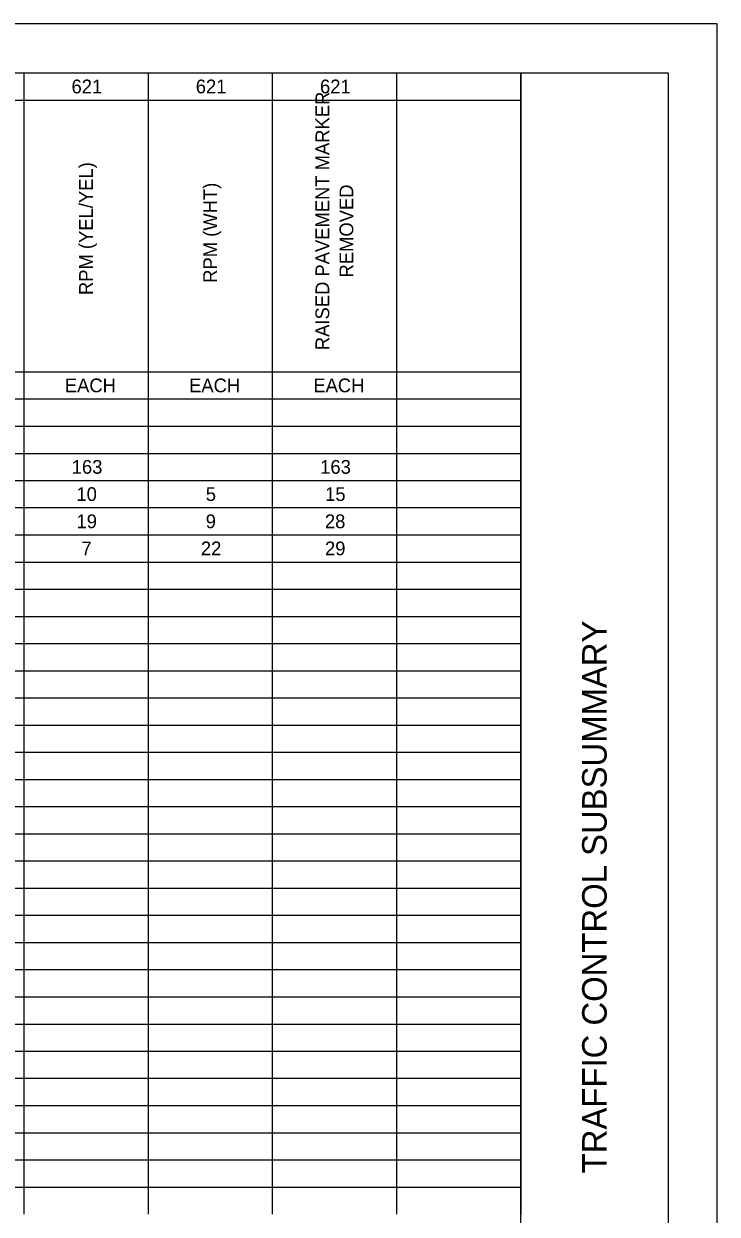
# Model space of a CAD drawing. Extents: x 0 to 34, y 0 to 22.
# Drawn here: x 26.94 to 34, y 9.88 to 22 of the extents above; entities that cross this region are included whole.
import ezdxf

# ---------------------------------------------------------------- set-up
doc = ezdxf.new("R2010")
doc.units = 0
for name, color, linetype in [('SH_Border', 7, 'Continuous'), ('SH_Cut_Line', 7, 'Continuous'), ('SH_Data', 7, 'Continuous'), ('SH_Text', 7, 'Continuous')]:
    doc.layers.add(name, color=color, linetype=linetype)

msp = doc.modelspace()

# ---------------------------------------------------------------- linework, layer by layer
at = {"layer": 'SH_Border'}
msp.add_line((32, 0.5), (32, 21.5), dxfattribs=at)
msp.add_lwpolyline([(1.5, 21.5), (33.5, 21.5), (33.5, 0.5), (1.5, 0.5)], close=True, dxfattribs=at)
at = {"layer": 'SH_Cut_Line'}
msp.add_lwpolyline([(0, 0), (34, 0), (34, 22), (0, 22)], close=True, dxfattribs=at)
at = {"layer": 'SH_Text'}
for p, q in [((25.675, 21.5), (26.94, 21.5)), ((26.94, 21.5), (28.205, 21.5)), ((26.94, 21.5), (26.94, 21.223)), ((28.205, 21.5), (29.47, 21.5)), ((28.205, 21.5), (28.205, 21.223)), ((29.47, 21.5), (30.735, 21.5)), ((29.47, 21.5), (29.47, 21.223)), ((30.735, 21.5), (32, 21.5)), ((30.735, 21.5), (30.735, 21.223)), ((32, 21.5), (32, 21.223)), ((25.675, 21.223), (26.94, 21.223)), ((26.94, 21.223), (28.205, 21.223)), ((26.94, 21.223), (26.94, 20.947)), ((28.205, 21.223), (29.47, 21.223)), ((28.205, 21.223), (28.205, 20.947)), ((29.47, 21.223), (30.735, 21.223)), ((29.47, 21.223), (29.47, 20.947)), ((30.735, 21.223), (32, 21.223)), ((30.735, 21.223), (30.735, 20.947)), ((32, 21.223), (32, 20.947)), ((26.94, 20.947), (26.94, 20.67)), ((28.205, 20.947), (28.205, 20.67)), ((29.47, 20.947), (29.47, 20.67)), ((30.735, 20.947), (30.735, 20.67)), ((32, 20.947), (32, 20.67)), ((26.94, 20.67), (26.94, 20.393)), ((28.205, 20.67), (28.205, 20.393)), ((29.47, 20.67), (29.47, 20.393)), ((30.735, 20.67), (30.735, 20.393)), ((32, 20.67), (32, 20.393)), ((26.94, 20.393), (26.94, 20.116)), ((28.205, 20.393), (28.205, 20.116)), ((29.47, 20.393), (29.47, 20.116)), ((30.735, 20.393), (30.735, 20.116)), ((32, 20.393), (32, 20.116)), ((26.94, 20.116), (26.94, 19.84)), ((28.205, 20.116), (28.205, 19.84)), ((29.47, 20.116), (29.47, 19.84)), ((30.735, 20.116), (30.735, 19.84)), ((32, 20.116), (32, 19.84)), ((26.94, 19.84), (26.94, 19.563)), ((28.205, 19.84), (28.205, 19.563)), ((29.47, 19.84), (29.47, 19.563)), ((30.735, 19.84), (30.735, 19.563)), ((32, 19.84), (32, 19.563)), ((26.94, 19.563), (26.94, 19.01)), ((28.205, 19.563), (28.205, 19.01)), ((29.47, 19.563), (29.47, 19.01)), ((30.735, 19.563), (30.735, 19.01)), ((32, 19.563), (32, 19.01)), ((26.94, 19.01), (26.94, 18.18)), ((28.205, 19.01), (28.205, 18.18)), ((29.47, 19.01), (29.47, 18.18)), ((30.735, 19.01), (30.735, 18.18)), ((32, 19.01), (32, 18.18)), ((25.675, 18.456), (26.94, 18.456)), ((26.94, 18.456), (28.205, 18.456)), ((28.205, 18.456), (29.47, 18.456)), ((29.47, 18.456), (30.735, 18.456)), ((30.735, 18.456), (32, 18.456)), ((25.675, 18.18), (26.94, 18.18)), ((26.94, 18.18), (28.205, 18.18)), ((26.94, 18.18), (26.94, 17.349)), ((28.205, 18.18), (29.47, 18.18)), ((28.205, 18.18), (28.205, 17.349)), ((29.47, 18.18), (30.735, 18.18)), ((29.47, 18.18), (29.47, 17.349)), ((30.735, 18.18), (32, 18.18)), ((30.735, 18.18), (30.735, 17.349)), ((32, 18.18), (32, 17.349)), ((25.675, 17.903), (26.94, 17.903)), ((26.94, 17.903), (28.205, 17.903)), ((28.205, 17.903), (29.47, 17.903)), ((29.47, 17.903), (30.735, 17.903)), ((30.735, 17.903), (32, 17.903)), ((25.675, 17.626), (26.94, 17.626)), ((26.94, 17.626), (28.205, 17.626)), ((28.205, 17.626), (29.47, 17.626)), ((29.47, 17.626), (30.735, 17.626)), ((30.735, 17.626), (32, 17.626)), ((25.675, 17.349), (26.94, 17.349)), ((26.94, 17.349), (28.205, 17.349)), ((26.94, 17.349), (26.94, 17.073)), ((28.205, 17.349), (29.47, 17.349)), ((28.205, 17.349), (28.205, 17.073)), ((29.47, 17.349), (30.735, 17.349)), ((29.47, 17.349), (29.47, 17.073)), ((30.735, 17.349), (32, 17.349)), ((30.735, 17.349), (30.735, 17.073)), ((32, 17.349), (32, 17.073)), ((25.675, 17.073), (26.94, 17.073)), ((26.94, 17.073), (28.205, 17.073)), ((26.94, 17.073), (26.94, 15.966)), ((28.205, 17.073), (29.47, 17.073)), ((28.205, 17.073), (28.205, 15.966)), ((29.47, 17.073), (30.735, 17.073)), ((29.47, 17.073), (29.47, 15.966)), ((30.735, 17.073), (32, 17.073)), ((30.735, 17.073), (30.735, 15.966)), ((32, 17.073), (32, 15.966)), ((25.675, 16.796), (26.94, 16.796)), ((26.94, 16.796), (28.205, 16.796)), ((28.205, 16.796), (29.47, 16.796)), ((29.47, 16.796), (30.735, 16.796)), ((30.735, 16.796), (32, 16.796)), ((25.675, 16.519), (26.94, 16.519)), ((26.94, 16.519), (28.205, 16.519)), ((28.205, 16.519), (29.47, 16.519)), ((29.47, 16.519), (30.735, 16.519)), ((30.735, 16.519), (32, 16.519)), ((25.675, 16.243), (26.94, 16.243)), ((26.94, 16.243), (28.205, 16.243)), ((28.205, 16.243), (29.47, 16.243)), ((29.47, 16.243), (30.735, 16.243)), ((30.735, 16.243), (32, 16.243)), ((25.675, 15.966), (26.94, 15.966)), ((26.94, 15.966), (28.205, 15.966)), ((26.94, 15.966), (26.94, 15.689)), ((28.205, 15.966), (29.47, 15.966)), ((28.205, 15.966), (28.205, 15.689)), ((29.47, 15.966), (30.735, 15.966)), ((29.47, 15.966), (29.47, 15.689)), ((30.735, 15.966), (32, 15.966)), ((30.735, 15.966), (30.735, 15.689)), ((32, 15.966), (32, 15.689)), ((25.675, 15.689), (26.94, 15.689)), ((26.94, 15.689), (28.205, 15.689)), ((26.94, 15.689), (26.94, 15.136)), ((28.205, 15.689), (29.47, 15.689)), ((28.205, 15.689), (28.205, 15.136)), ((29.47, 15.689), (30.735, 15.689)), ((29.47, 15.689), (29.47, 15.136)), ((30.735, 15.689), (32, 15.689)), ((30.735, 15.689), (30.735, 15.136)), ((32, 15.689), (32, 15.136)), ((25.675, 15.412), (26.94, 15.412)), ((26.94, 15.412), (28.205, 15.412)), ((28.205, 15.412), (29.47, 15.412)), ((29.47, 15.412), (30.735, 15.412)), ((30.735, 15.412), (32, 15.412)), ((25.675, 15.136), (26.94, 15.136)), ((26.94, 15.136), (28.205, 15.136)), ((26.94, 15.136), (26.94, 14.582)), ((28.205, 15.136), (29.47, 15.136)), ((28.205, 15.136), (28.205, 14.582)), ((29.47, 15.136), (30.735, 15.136)), ((29.47, 15.136), (29.47, 14.582)), ((30.735, 15.136), (32, 15.136)), ((30.735, 15.136), (30.735, 14.582)), ((32, 15.136), (32, 14.582)), ((25.675, 14.859), (26.94, 14.859)), ((26.94, 14.859), (28.205, 14.859)), ((28.205, 14.859), (29.47, 14.859)), ((29.47, 14.859), (30.735, 14.859)), ((30.735, 14.859), (32, 14.859)), ((25.675, 14.582), (26.94, 14.582)), ((26.94, 14.582), (28.205, 14.582)), ((26.94, 14.582), (26.94, 14.306)), ((28.205, 14.582), (29.47, 14.582)), ((28.205, 14.582), (28.205, 14.306)), ((29.47, 14.582), (30.735, 14.582)), ((29.47, 14.582), (29.47, 14.306)), ((30.735, 14.582), (32, 14.582)), ((30.735, 14.582), (30.735, 14.306)), ((32, 14.582), (32, 14.306)), ((25.675, 14.306), (26.94, 14.306)), ((26.94, 14.306), (28.205, 14.306)), ((26.94, 14.306), (26.94, 13.752)), ((28.205, 14.306), (29.47, 14.306)), ((28.205, 14.306), (28.205, 13.752)), ((29.47, 14.306), (30.735, 14.306)), ((29.47, 14.306), (29.47, 13.752)), ((30.735, 14.306), (32, 14.306)), ((30.735, 14.306), (30.735, 13.752)), ((32, 14.306), (32, 13.752)), ((25.675, 14.029), (26.94, 14.029)), ((26.94, 14.029), (28.205, 14.029)), ((28.205, 14.029), (29.47, 14.029)), ((29.47, 14.029), (30.735, 14.029)), ((30.735, 14.029), (32, 14.029)), ((25.675, 13.752), (26.94, 13.752)), ((26.94, 13.752), (28.205, 13.752)), ((26.94, 13.752), (26.94, 13.476)), ((28.205, 13.752), (29.47, 13.752)), ((28.205, 13.752), (28.205, 13.476)), ((29.47, 13.752), (30.735, 13.752)), ((29.47, 13.752), (29.47, 13.476)), ((30.735, 13.752), (32, 13.752)), ((30.735, 13.752), (30.735, 13.476)), ((32, 13.752), (32, 13.476)), ((25.675, 13.476), (26.94, 13.476)), ((26.94, 13.476), (28.205, 13.476)), ((26.94, 13.476), (26.94, 12.645)), ((28.205, 13.476), (29.47, 13.476)), ((28.205, 13.476), (28.205, 12.645)), ((29.47, 13.476), (30.735, 13.476)), ((29.47, 13.476), (29.47, 12.645)), ((30.735, 13.476), (32, 13.476)), ((30.735, 13.476), (30.735, 12.645)), ((32, 13.476), (32, 12.645)), ((25.675, 13.199), (26.94, 13.199)), ((26.94, 13.199), (28.205, 13.199)), ((28.205, 13.199), (29.47, 13.199)), ((29.47, 13.199), (30.735, 13.199)), ((30.735, 13.199), (32, 13.199)), ((25.675, 12.922), (26.94, 12.922)), ((26.94, 12.922), (28.205, 12.922)), ((28.205, 12.922), (29.47, 12.922)), ((29.47, 12.922), (30.735, 12.922)), ((30.735, 12.922), (32, 12.922)), ((25.675, 12.645), (26.94, 12.645)), ((26.94, 12.645), (28.205, 12.645)), ((26.94, 12.645), (26.94, 12.369)), ((28.205, 12.645), (29.47, 12.645)), ((28.205, 12.645), (28.205, 12.369)), ((29.47, 12.645), (30.735, 12.645)), ((29.47, 12.645), (29.47, 12.369)), ((30.735, 12.645), (32, 12.645)), ((30.735, 12.645), (30.735, 12.369)), ((32, 12.645), (32, 12.369)), ((25.675, 12.369), (26.94, 12.369)), ((26.94, 12.369), (28.205, 12.369)), ((26.94, 12.369), (26.94, 12.092)), ((28.205, 12.369), (29.47, 12.369)), ((28.205, 12.369), (28.205, 12.092)), ((29.47, 12.369), (30.735, 12.369)), ((29.47, 12.369), (29.47, 12.092)), ((30.735, 12.369), (32, 12.369)), ((30.735, 12.369), (30.735, 12.092)), ((32, 12.369), (32, 12.092)), ((25.675, 12.092), (26.94, 12.092)), ((26.94, 12.092), (28.205, 12.092)), ((26.94, 12.092), (26.94, 11.262)), ((28.205, 12.092), (29.47, 12.092)), ((28.205, 12.092), (28.205, 11.262)), ((29.47, 12.092), (30.735, 12.092)), ((29.47, 12.092), (29.47, 11.262)), ((30.735, 12.092), (32, 12.092)), ((30.735, 12.092), (30.735, 11.262)), ((32, 12.092), (32, 11.262)), ((25.675, 11.815), (26.94, 11.815)), ((26.94, 11.815), (28.205, 11.815)), ((28.205, 11.815), (29.47, 11.815)), ((29.47, 11.815), (30.735, 11.815)), ((30.735, 11.815), (32, 11.815)), ((25.675, 11.539), (26.94, 11.539)), ((26.94, 11.539), (28.205, 11.539)), ((28.205, 11.539), (29.47, 11.539)), ((29.47, 11.539), (30.735, 11.539)), ((30.735, 11.539), (32, 11.539)), ((25.675, 11.262), (26.94, 11.262)), ((26.94, 11.262), (28.205, 11.262)), ((26.94, 11.262), (26.94, 10.708)), ((28.205, 11.262), (29.47, 11.262)), ((28.205, 11.262), (28.205, 10.708)), ((29.47, 11.262), (30.735, 11.262)), ((29.47, 11.262), (29.47, 10.708)), ((30.735, 11.262), (32, 11.262)), ((30.735, 11.262), (30.735, 10.708)), ((32, 11.262), (32, 10.708)), ((25.675, 10.985), (26.94, 10.985)), ((26.94, 10.985), (28.205, 10.985)), ((28.205, 10.985), (29.47, 10.985)), ((29.47, 10.985), (30.735, 10.985)), ((30.735, 10.985), (32, 10.985)), ((25.675, 10.708), (26.94, 10.708)), ((26.94, 10.708), (28.205, 10.708)), ((26.94, 10.708), (26.94, 9.878)), ((28.205, 10.708), (29.47, 10.708)), ((28.205, 10.708), (28.205, 9.878)), ((29.47, 10.708), (30.735, 10.708)), ((29.47, 10.708), (29.47, 9.878)), ((30.735, 10.708), (32, 10.708)), ((30.735, 10.708), (30.735, 9.878)), ((32, 10.708), (32, 9.878)), ((25.675, 10.432), (26.94, 10.432)), ((26.94, 10.432), (28.205, 10.432)), ((28.205, 10.432), (29.47, 10.432)), ((29.47, 10.432), (30.735, 10.432)), ((30.735, 10.432), (32, 10.432)), ((25.675, 10.155), (26.94, 10.155)), ((26.94, 10.155), (28.205, 10.155)), ((28.205, 10.155), (29.47, 10.155)), ((29.47, 10.155), (30.735, 10.155)), ((30.735, 10.155), (32, 10.155))]:
    msp.add_line(p, q, dxfattribs=at)

# ---------------------------------------------------------------- texts
at = {"layer": 'SH_Data'}
msp.add_text('TRAFFIC CONTROL SUBSUMMARY', height=0.25, rotation=90, dxfattribs=at).set_placement((32.875, 10.295))
at = {"layer": 'SH_Text'}
for s, p in [('621', (27.426, 21.292)), ('621', (28.691, 21.292)), ('621', (29.956, 21.292)), ('EACH', (27.358, 18.248)), ('EACH', (28.623, 18.248)), ('EACH', (29.888, 18.248)), ('163', (27.428, 17.418)), ('163', (29.958, 17.418)), ('10', (27.476, 17.141)), ('5', (28.793, 17.141)), ('15', (30.008, 17.141)), ('19', (27.477, 16.864)), ('9', (28.792, 16.864)), ('28', (30.006, 16.864)), ('22', (28.743, 16.588)), ('29', (30.007, 16.588)), ('7', (27.527, 16.588))]:
    msp.add_text(s, height=0.14, dxfattribs=at).set_placement(p)
for s, p in [('RAISED PAVEMENT MARKER ', (30.05, 18.677)), ('RPM (YEL/YEL)', (27.643, 19.238)), ('RPM (WHT)', (28.908, 19.363)), ('REMOVED', (30.295, 19.417))]:
    msp.add_text(s, height=0.14, rotation=90, dxfattribs=at).set_placement(p)

doc.saveas('drawing.dxf')
